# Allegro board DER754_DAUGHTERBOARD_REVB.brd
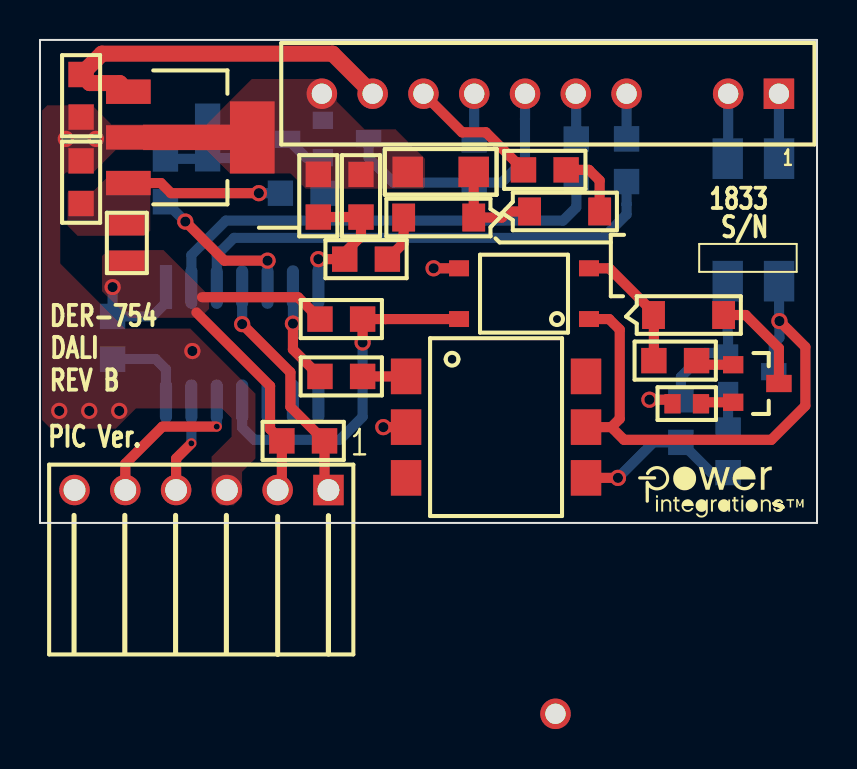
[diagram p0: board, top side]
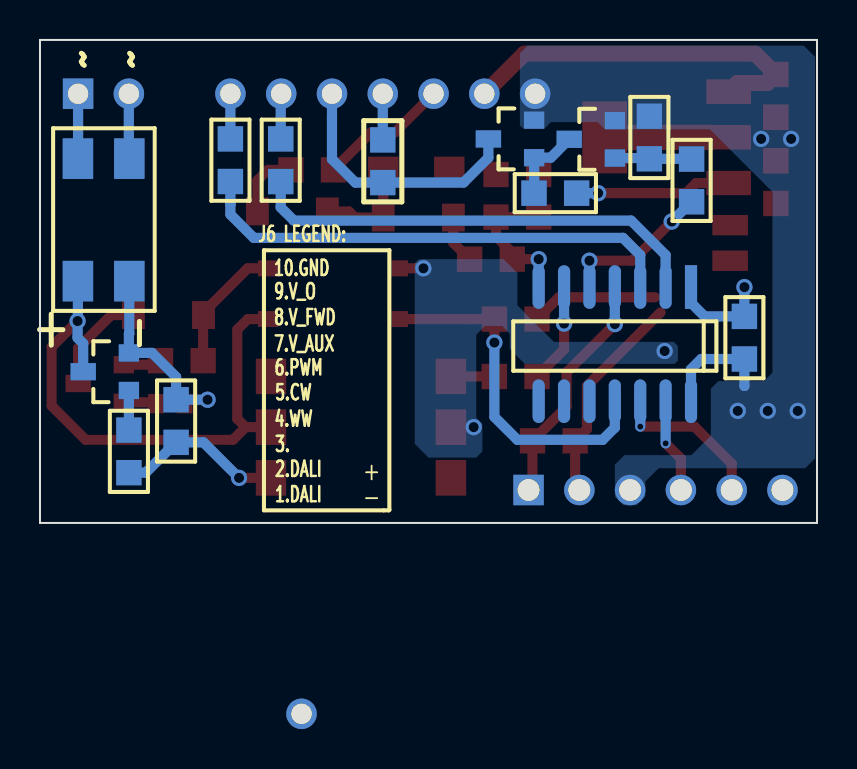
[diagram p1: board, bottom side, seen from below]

Outline 38.86 x 24.18 mm; copper layers: TOP, BOTTOM. Coordinates in mm from the lower left corner of the outline.
Outline path: 0,24.18 38.86,24.18 38.86,0 0,0 0,24.18

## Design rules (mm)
constraint set DEFAULT: min track width 0.508

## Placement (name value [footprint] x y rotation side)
BR2  MB6S  [PISMSOIC4]  34.4 18.23 0 bottom
C39  100 nF  [PISMC0805]  3.63 8.2 90 bottom
C40  1 uF  [PISMC0805]  2.06 22.45 270 top
C41  4.7 uF  [PISMC0805]  2.06 18.12 270 top
C42  100 nF  [PISMC1206]  21.69 17.57 180 top
C43  100 nF  [PISMC0805]  13.92 17.45 270 top
D1  BAV21W-7-F  [PI_SM_SOD-123_12]  24.49 15.59 0 top
J5  CON6  [PI_MOLEX_06_RA_22SERIES]  14.43 1.65 180 top
J6  CON10  [PI_MOLEX_10]  36.96 21.48 180 top
L4  560 nH  [PISMINDAISC0805]  4.34 14.9 270 top
NOREF  -  []  0 0 0 top
NOREF#2  -  []  38.86 0 90 top
NOREF#3  -  []  -228.55 -144.79 0 top
NOREF#4  -  []  -150.73 54.23 0 top
NOREF#5  -  []  29.36 2.74 0 top
Q7  2N7002  [PISMSOT23123_1]  10.11 20.14 90 bottom
Q8  FMMT459TA  [PISMSOT23123_1]  34.42 8.51 90 bottom
Q9  FMMT459TA  [PISMSOT23123_1]  34.67 6.04 270 top
Q10  PMV16XNR  [PISMSOT23123_1]  14.15 20.16 90 bottom
R50  47  [PISMR0805]  6.27 16.08 90 bottom
R51  10 k  [PISMR0805]  8.39 20.36 270 bottom
R52  820  [PISMR0805]  12.02 16.51 0 bottom
R53  10 k  [PISMR0805]  14 10.2 0 top
R54  330  [PISMR0805]  14 7.33 0 top
R55  1.00 k  [PISMR0805]  32.06 4.03 90 bottom
R56  120  [PISMR0805]  34.42 2.52 90 bottom
R57  100 k  [PISMR0805]  32.84 8.12 180 top
R64  10 k  [PISMR0805]  12.1 4.11 0 top
R66  240  [PISMR0603]  33.06 5.97 180 top
R68  100  [PISMR0805]  26.82 17.09 90 bottom
R69  100  [PISMR0805]  29.34 19.22 270 bottom
R70  47  [PISMR0805]  24.18 17.67 0 top
R71  499 k  [PISMR0805]  17.38 13.2 180 top
R72  42.2 k  [PISMR0805]  16.05 15.31 90 top
R73  3 k  [PISMR0805]  21.72 19.17 270 bottom
U11  NCV4264-2ST50T3G  [PI_SM_SOT_223_1234]  10.62 19.3 270 top
U12  LTV-356T  [PI_4_SMD_LTV356]  27.46 10.21 90 top
U13  MOC8204SR2M  [PI_6_SMD]  22.81 4.8 270 top
U16  PIC16F18326-I/SL  [PISOG05014WB300L400]  6.3 11.81 0 bottom
VR7  MMSZ5230B-7-F  [PI_SM_SOD-123_12]  30.69 10.41 0 top
VR8  BZT52C15-7-F  [PI_SM_SOD-123_12]  21.69 15.29 180 top

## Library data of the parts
BR2 = DIODE BRIDGE_~~+-: alternate symbols: (pi_sm_soic4_slot)
C39-C43 = CAP NP
D1 = DIODE
J5 = CON6
J6 = CON10
L4 = INDUCTOR
Q7 Q10 = FET_N_GSD
Q8 Q9 = NPN_BEC
R50-R57 R64 R66 R68-R73 = R
U11 = NCV4264
U12 = OPTO_A_B
U13 = OPTO_A_B_Base
U16 = PIC16F18326-I/SL
VR7 VR8 = DIODE_ZENER

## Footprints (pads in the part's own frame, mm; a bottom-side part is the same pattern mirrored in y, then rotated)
PI_4_SMD_LTV356
  rect 0.8x1 smd: 1(0,0) 2(2.54,0) 3(2.54,6.5) 4(0,6.5)
PI_6_SMD
  rect 1.78x1.52 smd: 1(-2.54,-4.5) 2(0,-4.5) 3(2.54,-4.5) 4(2.54,4.5) 5(0,4.5) 6(-2.54,4.5)
PI_MOLEX_06_RA_22SERIES
  rect 1.524x1.524 hole 1.092: 1(0,0)
  round 1.524 hole 1.092: 2(2.54,0) 3(5.08,0) 4(7.62,0) 5(10.16,0) 6(12.7,0)
PI_MOLEX_10
  rect 1.524x1.524 hole 1.016: 1(0,0)
  round 1.524 hole 1.016: 2(2.54,0) 3(11.176,31.039) 4(7.62,0) 5(10.16,0) 6(12.7,0) 7(15.24,0) 8(17.78,0) 9(20.32,0) 10(22.86,0)
PI_SM_SOD-123_12
  rect 1.143x1.397 smd: 1(0,0) 2(3.505,0)
PI_SM_SOT_223_1234
  rect 1.219x2.235 smd: 1(-2.286,-6.198) 2(0,-6.198) 3(2.286,-6.198)
  rect 3.607x2.235 smd: 4(0,0)
PISMC0805
  rect 1.27x1.27 smd: 1(0,0) 2(2.134,0)
PISMC1206
  rect 1.524x1.524 smd: 1(0,0) 2(3.302,0)
PISMINDAISC0805
  rect 1.02x1.78 smd: 1(0,0) 2(1.78,0)
PISMR0603
  rect 0.813x0.965 smd: 1(0,0) 2(1.422,0)
PISMR0805
  rect 1.27x1.27 smd: 1(0,0) 2(2.134,0)
PISMSOIC4
  rect 1.524x2.032 smd: 1(0,0) 2(2.571,0) 3(2.571,6.129) 4(0,6.129)
PISMSOT23123_1
  rect 0.864x1.016 smd: 1(-1.88,0) 2(0,0)
  rect 0.864x1.27 smd: 3(-0.94,2.286)
PISOG05014WB300L400
  rect 0.61x2.184 smd: 1(0,0)
  oval 0.61x2.184 smd: 2(1.27,0) 3(2.54,0) 4(3.81,0) 5(5.08,0) 6(6.35,0) 7(7.62,0) 8(7.62,5.715) 9(6.35,5.715) 10(5.08,5.715) 11(3.81,5.715) 12(2.54,5.715) 13(1.27,5.715) 14(0,5.715)

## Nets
GND: C39.1 C40.2 C41.1 C42.2 C43.1 J5.3 J6.10 Q7.2(S) Q10.2(S) R51.1 R72.2 U11.2 U11.4 U12.3(E) U13.2 U16.14(VSS)
VDD: C39.2 J5.2 L4.2 R53.1 R64.1 U16.1
COMP_IN: C43.2 R71.2 R72.1 U16.7
CW: J6.5 R68.2
DALI +: BR2.1 J6.2
DALI -: BR2.2 J6.1
PWM: J6.6 Q10.3 R73.2
RA0: J5.4 U16.13
RA1: J5.5 U16.12
RA3: J5.1 R64.2 U16.4
V_AUX: J6.7 R73.1
V_FWD: J6.8 R70.1
V_O: C40.1 J6.9 U11.1
WW: J6.4 R69.1
N11807834: R54.2 U13.1
N11807846: BR2.3 Q8.3 U12.1 U13.5
N11807918: R55.1 R56.1 U13.4(E)
N11807964: Q8.1 R56.2
N11807986: BR2.4 Q8.2(EMITTER) R55.2 R66.2
N11807994: C41.2 L4.1 R52.1 U11.3(OUT)
N11807998: R53.2 U12.4 U16.11
N11808486: R57.2 U12.2 VR7.1
N11808610: Q7.1 R50.2 R51.2
N11808638: Q7.3 Q10.1 R52.2
N11850613: R54.1 U16.6
N11856301: R50.1 U16.5
N11857036: Q9.3 VR7.2
N11857044: Q9.1 R57.1
N11857111: Q9.2(EMITTER) R66.1
N11914189: R68.1 U16.2
N11914225: R69.2 U16.3
N11915617: D1.2 R70.2
N11915634: C42.1 D1.1 VR8.1
N11915686: R71.1 VR8.2

Pads without a net: J5 6; J6 3; U13 3 6; U16 8 9 10

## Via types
v1: diameter 0.813, hole 0.508, TOP to BOTTOM, 19 vias
v2: diameter 0.457, hole 0.305, TOP to BOTTOM, 2 vias

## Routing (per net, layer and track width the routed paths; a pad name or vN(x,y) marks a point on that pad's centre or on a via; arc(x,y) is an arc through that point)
GND: length 8.2
  TOP w0.508: U13.2 v1(17.17,4.8) ; U12.3 v1(19.69,12.75)
  BOTTOM w0.508: 3.63,6.85 3.63,6.85 C39.1 5.79,8.2 6.3,7.69 U16.14
  vias: v1(0.96,5.61) v1(1.29,19.22) v1(2.46,5.61) v1(2.79,19.22) v1(3.96,5.61) v1(7.62,8.61)
VDD: length 22.3
  TOP w0.508: R53.1 12.91,11.3 8.1,11.3 ; J5.2 12.1,1.86 R64.1 11.51,4.7 11.51,6.85 7.82,10.54
  BOTTOM w0.508: v1(3.63,11.8) C39.2 5.62,10.34 6.3,11.02 U16.1
COMP_IN: length 7.3
  TOP w0.508: v1(13.92,13.2) R71.2 15.24,13.53 16.05,14.35 R72.1 C43.2
  BOTTOM w0.508: U16.7 v1(13.92,13.2)
CW: length 2.3
  BOTTOM w0.508: R68.2 26.82,21.46 J6.5 26.77,21.46
DALI +: length 3.3
  BOTTOM w0.508: BR2.1 34.42,18.26 J6.2
DALI -: length 3.3
  BOTTOM w0.508: BR2.2 36.96,18.24 J6.1
PWM: length 13
  BOTTOM w0.508: Q10.3 16.44,18.28 17.68,17.04 R73.2 23.09,17.04 24.26,18.21 24.26,20.21 24.26,20.21 J6.6
RA0: length 4.8
  TOP w0.508: v2(7.57,3.98) 6.81,3.22 J5.4
  BOTTOM w0.508: U16.13 v2(7.57,3.98)
RA1: length 7.9
  TOP w0.508: v2(8.84,4.82) 6.12,4.82 4.27,2.96 J5.5
  BOTTOM w0.508: U16.12 v2(8.84,4.82)
RA3: length 11.9
  TOP w0.508: v1(10.11,9.95) 12.52,7.54 12.52,5.82 R64.2 14.23,1.84 J5.1
  BOTTOM w0.508: U16.4 v1(10.11,9.95)
V_AUX: length 2.3
  BOTTOM w0.508: R73.1 21.72,21.48 J6.7
V_FWD: length 6.6
  TOP w0.508: R70.1 22.3,19.55 21.11,19.55 J6.8
V_O: length 18.6
  TOP w0.8: J6.9 14.63,23.49 3.1,23.49 C40.1 2.49,22.02 3.99,22.02 U11.1
WW: length 2.3
  BOTTOM w0.508: R69.1 J6.4
N11807834: length 2.2
  TOP w0.508: R54.2 16.16,7.33 16.16,7.34 U13.1
N11807846: length 28.2
  TOP w0.508: v1(36.98,10.1) 38.28,8.81 38.28,5.86 36.58,4.16 29.21,4.16 28.58,4.79 28.58,4.8 ; U12.1 28.47,10.21 29,9.68 29,5.21 28.58,4.8 ; 28.58,4.8 U13.5
  BOTTOM w0.508: BR2.3 36.97,10.12 v1(36.98,10.1) 36.98,9.27 36.7,8.98 Q8.3
N11807918: length 8.5
  TOP w0.508: U13.4 v1(28.91,2.26)
  BOTTOM w0.508: v1(28.91,2.26) 30.68,4.03 R55.1 33.57,2.52 R56.1
N11807964: length 2
  BOTTOM w0.508: Q8.1 R56.2
N11807986: length 10.4
  TOP w0.508: R66.2 31.44,6.17 v1(30.48,6.17)
  BOTTOM w0.508: BR2.4 34.4,9.47 34.42,9.45 Q8.2 33.26,8.51 32.06,7.31 R55.2 v1(30.48,6.17)
N11807994: length 7.8
  TOP w0.508: v1(10.95,16.51) 6.55,16.51 6.05,17.01 U11.3
  BOTTOM w0.508: R52.1 v1(10.95,16.51)
N11807998: length 17.8
  TOP w0.508: U12.4 17.28,10.21 17.28,10.2 R53.2 v1(16.14,9.03)
  BOTTOM w0.508: v1(16.14,9.03) 16.14,5.31 14.99,4.16 10.72,4.16 10.11,4.77 U16.11
N11808486: length 6.6
  TOP w0.508: R57.2 30.7,10.39 VR7.1 30.69,10.53 28.47,12.75 U12.2
N11808610: length 3.9
  BOTTOM w0.508: R50.2 6.29,18.23 R51.2 8.42,18.26 Q7.1
N11808638: length 3.9
  BOTTOM w0.508: R52.2 14.15,16.51 Q10.1 13.31,18.28 Q7.3
N11850613: length 5
  TOP w0.508: v1(12.65,9.98) 12.65,8.68 R54.1
  BOTTOM w0.508: U16.6 v1(12.65,9.98)
N11856301: length 7.7
  TOP w0.508: v1(11.38,13.13) 9.22,13.13 v1(7.27,15.08)
  BOTTOM w0.508: R50.1 v1(7.27,15.08) ; U16.5 v1(11.38,13.13)
N11857036: length 5.2
  TOP w0.508: Q9.3 36.96,8.75 35.3,10.41 VR7.2
N11857044: length 1.9
  TOP w0.508: Q9.1 33.04,7.92 R57.1
N11857111: length 1.6
  TOP w0.508: Q9.2 33.13,6.04 R66.1
N11914189: length 23.1
  BOTTOM w0.508: U16.2 7.57,13.41 9.3,15.13 26.16,15.13 26.82,15.79 26.82,17.09 R68.1
N11914225: length 24.6
  BOTTOM w0.508: U16.3 8.84,13.41 9.7,14.27 28.17,14.27 29.34,15.44 29.34,15.95 29.34,15.95 R69.2
N11915617: length 3.4
  TOP w0.508: R70.2 27.46,17.67 27.99,17.14 D1.2
N11915634: length 5.2
  TOP w0.508: C42.1 VR8.1 23.1,15.29 23.41,15.59 D1.1
N11915686: length 2.4
  TOP w0.508: VR8.2 18.19,14.02 R71.1

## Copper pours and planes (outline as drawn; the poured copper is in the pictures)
GND on TOP (solid shape): 9.98,18.66 5.16,18.66 5.16,19.93 9.98,19.93
GND on TOP: 3.79,4.72 4.8,5.74 9.09,5.74 9.58,5.25 9.58,4.31 8.59,3.32 8.59,1.32 9.02,0.88 9.68,0.88 10.11,1.32 10.11,2.56 10.77,3.22 10.77,6.47 7.52,9.72 4.27,9.72 1.02,12.97 1.02,17.27 1.3,17.55 2.67,17.55 3.79,18.66 8.33,18.66 9.5,17.5 12.52,17.5 13.29,16.73 19.15,16.73 19.25,16.83 19.25,18.23 17.78,19.71 16.23,19.71 14.83,21.1 14.83,21.64 14.25,22.22 10.59,22.22 8.31,19.93 3.58,19.93 2.62,20.9 0.36,20.9 0.1,20.64 0.1,5.15 0.53,4.72
GND on BOTTOM: 5.31,4.36 5.31,6.71 4.92,7.1 2.65,7.1 2.23,7.52 2.23,16.57 5.36,19.71 10.62,19.71 10.97,20.06 13.31,20.06 13.64,19.73 14.68,19.73 14.86,19.91 14.86,23.52 14.48,23.9 0.66,23.9 0.1,23.34 0.1,3.22 0.59,2.74 7.93,2.74 8.59,2.08 8.59,1.32 9.02,0.88 9.68,0.88 10.11,1.32 10.11,2.92 9.63,3.4 6.28,3.4
GND on BOTTOM: 13.16,9.06 7.16,9.06 6.96,8.86 6.96,8.12 7.11,7.97 14.63,7.97 15.37,8.71 15.37,9.47 15.75,9.85 16.61,9.85 17.04,9.42 17.04,5.28 16.74,4.97 16.74,3.58 17.04,3.27 19.43,3.27 20.12,3.96 20.12,13 19.91,13.2 15.67,13.2 14.99,12.52 14.99,10.89
VDD on TOP: 3.1,13.36 3.1,11.6 4.43,10.27 8.02,10.27 8.46,10.71 8.46,11.37 6.17,13.66 3.4,13.66
N11807994 on TOP: 5.26,14.37 5.51,14.63 5.51,17.44 5.39,17.57 3.63,17.57 2.67,16.61 1.45,16.61 1.37,16.53 1.37,14.88 1.88,14.37

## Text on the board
Ref Des/Silkscreen Bottom: 5.CW | 3. | 2.DALI | 1.DALI | 6.PWM | 4.WW | 10.GND | 9.V_O | 8.V_FWD | 7.V_AUX | J6 LEGEND:
Ref Des/Silkscreen Top: 1 | PIC Ver. | DER-754 | REV B | DALI | 1833 | S/N
User.6: 14.  FAB HOUSE LOGO,DATE CODE TO BE IN SILK SCREEN ONLY.DO NOT USE COPPER. | 13.  MATERIAL FR4 COPPER 1oz THICKNESS 0.039"
User.8: FIGURE | FINISHED_SIZE | 12.0 | 20.0 | 40.0 | 43.0 | DRILL CHART: TOP to BOTTOM | ALL UNITS ARE IN MILS | PLATED | QTY | 2 | 19 | 10 | 6
